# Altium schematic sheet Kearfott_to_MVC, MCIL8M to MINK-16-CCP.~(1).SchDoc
size A
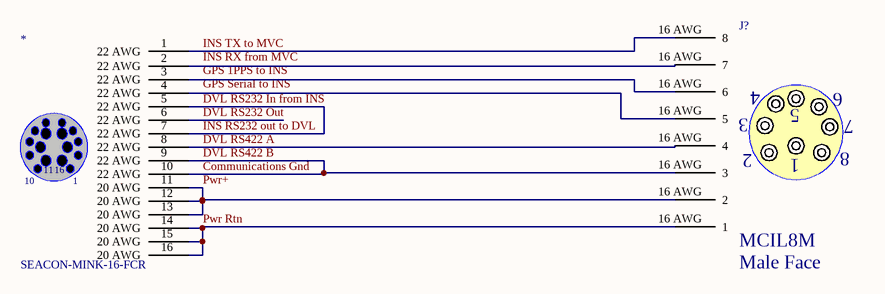
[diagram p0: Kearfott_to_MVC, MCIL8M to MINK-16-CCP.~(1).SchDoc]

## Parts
*  SEACON-MINK-16-FCR
J?  MCIL8M  View: Male Face

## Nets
Communications Gnd: *.9(22_AWG) *.10(22_AWG) J?.16_AWG(3)  [also labelled DVL RS422 B]
DVL RS232 In from INS: *.5(22_AWG) *.7(22_AWG)  [also labelled INS RS232 out to DVL]
DVL RS232 Out: *.6(22_AWG)
DVL RS422 A: *.8(22_AWG) J?.16_AWG(4)
INS TX to MVC: *.1(22_AWG) J?.16_AWG(8)
Pwr Rtn: *.14(20_AWG) *.15(20_AWG) *.16(20_AWG) J?.16_AWG(1)
Pwr+: *.11(20_AWG) *.12(20_AWG) *.13(20_AWG) J?.16_AWG(2)
Net*_2: *.2(22_AWG) J?.16_AWG(7)
Net*_3: *.3(22_AWG) J?.16_AWG(6)
Net*_4: *.4(22_AWG) J?.16_AWG(5)

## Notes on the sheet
- Labels drawn without touching a wire or pin: GPS 1PPS to INS, GPS Serial to INS, INS RX from MVC

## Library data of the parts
* = SEACON-MINK-16-FCR: Seacon MINK-16 FCR
J? = SUBCONN-MCxx8M: Subconn MCIL8M Connector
